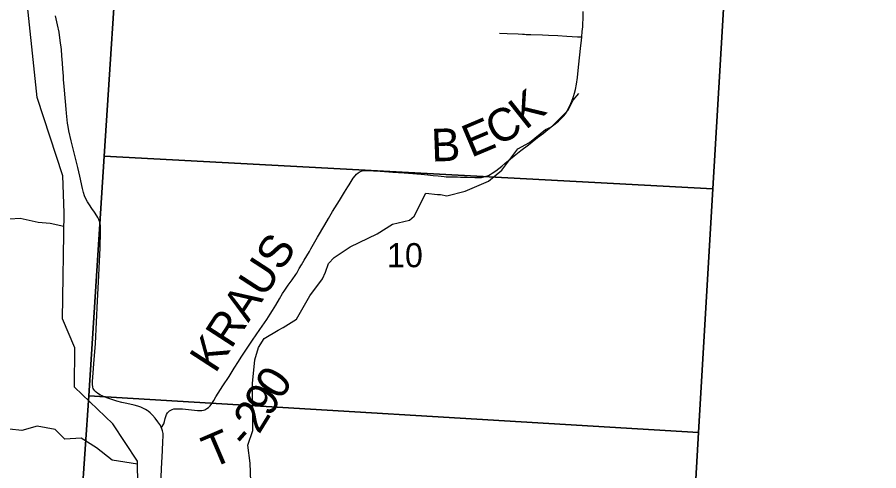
# Model space of a CAD drawing. Extents: x 0 to 34, y 0 to 22.
# Drawn here: x 25.392 to 26.889, y 19.146 to 19.934 of the extents above; entities that cross this region are included whole.
import ezdxf

# ---------------------------------------------------------------- set-up
doc = ezdxf.new("R2010")
doc.units = 0
for name, color, linetype in [('GM_X_County_Road', 7, 'Continuous'), ('GM_X_Minor_River', 7, 'Continuous'), ('GM_X_Section', 7, 'Continuous'), ('GM_X_Section_Text', 7, 'Continuous'), ('GM_X_Township_Road', 7, 'Continuous'), ('GM_X_Township_Road_Text', 7, 'Continuous')]:
    doc.layers.add(name, color=color, linetype=linetype)

msp = doc.modelspace()

# ---------------------------------------------------------------- linework, layer by layer
at = {"layer": 'GM_X_County_Road'}
for points in [[(25.6178, 19.2503), (25.6153, 19.252), (25.6115, 19.2541), (25.6068, 19.2561), (25.6015, 19.258), (25.5954, 19.2596), (25.5827, 19.2624), (25.5737, 19.2645), (25.565, 19.2668), (25.5528, 19.2706), (25.5493, 19.2718), (25.5431, 19.2742), (25.5397, 19.2758), (25.5369, 19.2772), (25.5324, 19.2799), (25.5294, 19.2822), (25.5272, 19.2844), (25.5254, 19.2867), (25.5243, 19.2887), (25.5234, 19.2913), (25.523, 19.2961), (25.5231, 19.301), (25.5243, 19.3158), (25.5255, 19.3313), (25.5279, 19.3667), (25.5319, 19.4411), (25.534, 19.4852), (25.5346, 19.4976), (25.5362, 19.533), (25.537, 19.5616), (25.5367, 19.572), (25.5363, 19.5748), (25.5358, 19.5775), (25.5348, 19.5802), (25.534, 19.5822), (25.5322, 19.5855), (25.5307, 19.5885), (25.5267, 19.5951), (25.5219, 19.6017), (25.5175, 19.6077), (25.5141, 19.6128), (25.5113, 19.6182), (25.5092, 19.6233), (25.5073, 19.6292), (25.5054, 19.6363), (25.5008, 19.6576), (25.4991, 19.6649), (25.4973, 19.6727), (25.4891, 19.7053), (25.4857, 19.7191), (25.482, 19.7361), (25.4806, 19.744), (25.4797, 19.7495), (25.4777, 19.7673), (25.4771, 19.7741), (25.4761, 19.7871), (25.474, 19.8131), (25.4728, 19.8254), (25.4723, 19.8315), (25.4713, 19.8441), (25.4707, 19.8539), (25.4698, 19.8669), (25.4688, 19.8775), (25.4669, 19.8935), (25.4648, 19.9077), (25.4623, 19.9205), (25.4588, 19.9363)], [(25.6415, 19.1182), (25.643, 19.1499), (25.6444, 19.1803), (25.6453, 19.197), (25.6457, 19.2051), (25.6455, 19.2108), (25.6447, 19.2152), (25.6436, 19.2189), (25.6425, 19.2215), (25.6421, 19.2224), (25.6399, 19.2263), (25.6367, 19.2309), (25.6316, 19.2373), (25.627, 19.2424), (25.623, 19.2464), (25.6195, 19.2492), (25.6178, 19.2503)]]:
    msp.add_lwpolyline(points, dxfattribs=at)
at = {"layer": 'GM_X_Minor_River'}
for points in [[(25.6073, 18.8574), (25.5886, 18.9702), (25.6029, 19.0352), (25.6012, 19.1623), (25.5582, 19.2276), (25.4917, 19.2911), (25.4923, 19.3594), (25.4708, 19.4097), (25.4737, 19.5938), (25.4713, 19.6579), (25.427, 19.7941), (25.4053, 19.9981), (25.349, 20.1513), (25.3065, 20.2086), (25.115, 20.2805), (25.1008, 20.2933), (25.0631, 20.3317), (24.9228, 20.3456), (24.7364, 20.2301), (24.7153, 20.2204)], [(25.7993, 19.0946), (25.797, 19.1588), (25.7929, 19.19), (25.8016, 19.2158), (25.8009, 19.2976), (25.8051, 19.3386), (25.8115, 19.3599), (25.8214, 19.3755), (25.8453, 19.39), (25.854, 19.3949), (25.8775, 19.4094), (25.9006, 19.4497), (25.9226, 19.479), (25.9275, 19.4908), (25.9332, 19.5056), (25.9427, 19.5163), (25.9704, 19.5349), (26.0174, 19.5574), (26.0443, 19.5742), (26.0735, 19.5811), (26.0815, 19.5883), (26.1023, 19.6282), (26.1224, 19.626), (26.1277, 19.6256), (26.1387, 19.6233), (26.1706, 19.6313), (26.2111, 19.6492), (26.2343, 19.6679), (26.262, 19.7052), (26.2821, 19.7158), (26.3101, 19.7387), (26.3204, 19.7432), (26.3492, 19.7722), (26.3579, 19.7897), (26.3681, 19.8015)], [(25.4733, 19.5703), (25.4496, 19.5754), (25.4283, 19.5769), (25.3973, 19.5841), (25.3794, 19.583)], [(25.6013, 19.157), (25.5571, 19.1643), (25.5298, 19.1859), (25.5033, 19.2022), (25.4748, 19.2007), (25.4578, 19.2177), (25.4271, 19.223), (25.4002, 19.2158), (25.3566, 19.2203)]]:
    msp.add_lwpolyline(points, dxfattribs=at)
at = {"layer": 'GM_X_Section'}
for points in [[(24.5388, 20.1708), (25.5703, 20.1097), (25.5433, 19.6923), (25.5164, 19.2759), (25.5041, 19.0909), (25.5038, 19.0874), (24.9075, 19.1174), (24.4668, 19.1382), (24.4804, 19.3317), (24.5096, 19.7459)], [(25.5703, 20.1097), (26.6253, 20.056), (26.6008, 19.6356), (25.5433, 19.6923)], [(27.6689, 20.0112), (27.6061, 18.9865), (26.5652, 19.0298), (26.5757, 19.2125), (26.6008, 19.6356), (26.6253, 20.056)], [(26.6008, 19.6356), (26.5757, 19.2125), (25.5164, 19.2759), (25.5433, 19.6923)], [(25.5164, 19.2759), (26.5757, 19.2125), (26.5652, 19.0298), (25.5041, 19.0909)]]:
    msp.add_lwpolyline(points, close=True, dxfattribs=at)
at = {"layer": 'GM_X_Township_Road'}
for points in [[(26.3219, 19.7449), (26.3242, 19.7468), (26.3325, 19.7533), (26.3348, 19.7553), (26.3383, 19.7589), (26.3412, 19.7619), (26.3444, 19.7657), (26.3476, 19.7704), (26.3501, 19.7756), (26.352, 19.7795), (26.3554, 19.7878), (26.3587, 19.796), (26.3605, 19.8017), (26.3621, 19.8083), (26.3638, 19.8174), (26.3655, 19.8291), (26.3675, 19.8469), (26.3713, 19.8846), (26.3723, 19.8932), (26.3728, 19.8994), (26.3737, 19.9087), (26.3746, 19.9172), (26.3749, 19.9234), (26.3751, 19.9302), (26.3754, 19.9438)], [(26.2302, 19.9061), (26.2433, 19.9055), (26.2624, 19.9046), (26.2698, 19.9042), (26.2735, 19.9041), (26.2765, 19.904), (26.279, 19.9039), (26.2845, 19.9038), (26.305, 19.9032), (26.3149, 19.9025), (26.3316, 19.9017), (26.3471, 19.9009), (26.3656, 19.8999), (26.3728, 19.8994)], [(26.1532, 19.6563), (26.1572, 19.6562), (26.1622, 19.6561), (26.1671, 19.6561), (26.171, 19.656), (26.174, 19.6558), (26.187, 19.6551), (26.1938, 19.6551), (26.1987, 19.6555), (26.2029, 19.6562), (26.207, 19.6574), (26.211, 19.659), (26.2137, 19.6604), (26.2174, 19.6627), (26.2234, 19.6671), (26.2338, 19.6749), (26.2395, 19.6796), (26.2491, 19.6876), (26.2554, 19.6927), (26.2671, 19.7019), (26.2802, 19.7123), (26.2865, 19.7173), (26.2963, 19.7249), (26.3062, 19.7325), (26.3111, 19.7363), (26.3219, 19.7449)], [(25.6556, 19.2488), (25.6568, 19.2499), (25.6589, 19.2513), (25.6612, 19.2524), (25.6643, 19.2532), (25.6674, 19.2536), (25.6711, 19.2536), (25.6792, 19.2531), (25.7001, 19.2509), (25.7055, 19.2503), (25.7099, 19.2503), (25.7131, 19.2504), (25.7157, 19.251), (25.718, 19.2517), (25.7218, 19.2537), (25.7244, 19.2559), (25.7272, 19.2588), (25.7302, 19.2627), (25.7337, 19.2681), (25.7373, 19.2743), (25.7413, 19.2806), (25.7494, 19.2931), (25.7602, 19.3098), (25.7692, 19.324), (25.7765, 19.3355), (25.7815, 19.3434), (25.7882, 19.3537), (25.8011, 19.3726), (25.8138, 19.391), (25.8258, 19.4084), (25.8318, 19.4178), (25.8358, 19.4241), (25.8415, 19.4337), (25.8478, 19.4444), (25.8532, 19.4535), (25.8569, 19.4593), (25.8628, 19.468), (25.8696, 19.4776), (25.876, 19.4865), (25.8777, 19.4891), (25.8798, 19.4928), (25.8821, 19.497), (25.8858, 19.5034), (25.8908, 19.5119), (25.8997, 19.5269), (25.9022, 19.5312), (25.9139, 19.5516), (25.9264, 19.5731), (25.9327, 19.5838), (25.94, 19.5961), (25.9521, 19.6154), (25.961, 19.6296), (25.9668, 19.6391), (25.9686, 19.6423), (25.9722, 19.6481), (25.9758, 19.6539), (25.9791, 19.6584), (25.9813, 19.6608), (25.9842, 19.6632), (25.9863, 19.6646), (25.9885, 19.6656), (25.9915, 19.6666), (25.9951, 19.6672), (25.9995, 19.6675), (26.0047, 19.6673), (26.0112, 19.6667), (26.0226, 19.666), (26.0378, 19.6649), (26.0446, 19.6645), (26.0644, 19.6631), (26.0941, 19.6608), (26.1053, 19.6597), (26.1149, 19.6588), (26.1233, 19.6579), (26.1337, 19.6571), (26.1374, 19.6567), (26.1423, 19.6566), (26.1532, 19.6563)], [(25.6425, 19.2215), (25.644, 19.2229), (25.646, 19.2255), (25.6468, 19.2273), (25.648, 19.2312), (25.6492, 19.2365), (25.6503, 19.2401), (25.6517, 19.2436), (25.6534, 19.2463), (25.655, 19.2482), (25.6556, 19.2488)]]:
    msp.add_lwpolyline(points, dxfattribs=at)

# ---------------------------------------------------------------- texts
at = {"layer": 'GM_X_Section_Text'}
msp.add_text('10', height=0.04186, rotation=0, dxfattribs=at).set_placement((26.0346, 19.4994))
at = {"layer": 'GM_X_Township_Road_Text'}
for s, height, rotation, p in [('K', 0.0568, 38.4708, (26.2753, 19.737)), ('C', 0.0568, 28.8789, (26.2258, 19.7087)), ('E', 0.0568, 22.8819, (26.1808, 19.6893)), ('B', 0.0568, 2.069, (26.1122, 19.6828)), ('KRAUS', 0.05682, 57.0662, (25.7362, 19.3135)), ('0', 0.0568, 56.9277, (25.8495, 19.2667)), ('9', 0.0568, 57.0734, (25.8305, 19.2373)), ('2', 0.0568, 58.3651, (25.8123, 19.2078)), ('T', 0.0568, 23.1688, (25.7294, 19.1491)), ('-', 0.0568, 48.5922, (25.7906, 19.1818))]:
    msp.add_text(s, height=height, rotation=rotation, dxfattribs=at).set_placement(p)

doc.saveas('drawing.dxf')
